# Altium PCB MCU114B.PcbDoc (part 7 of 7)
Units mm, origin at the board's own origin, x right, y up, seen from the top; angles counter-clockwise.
Board outline 105.51 x 58.76 mm, 8 copper layers (Top Layer, GND 2, Signal Layer 3, Power 4, Power 5, Signal Layer 6, GND 7, Bottom), stack 1.554 mm thick; 444 components, 418 nets, 1811 pads, 981 vias.
Unrouted connection lines stored in the file: 3.
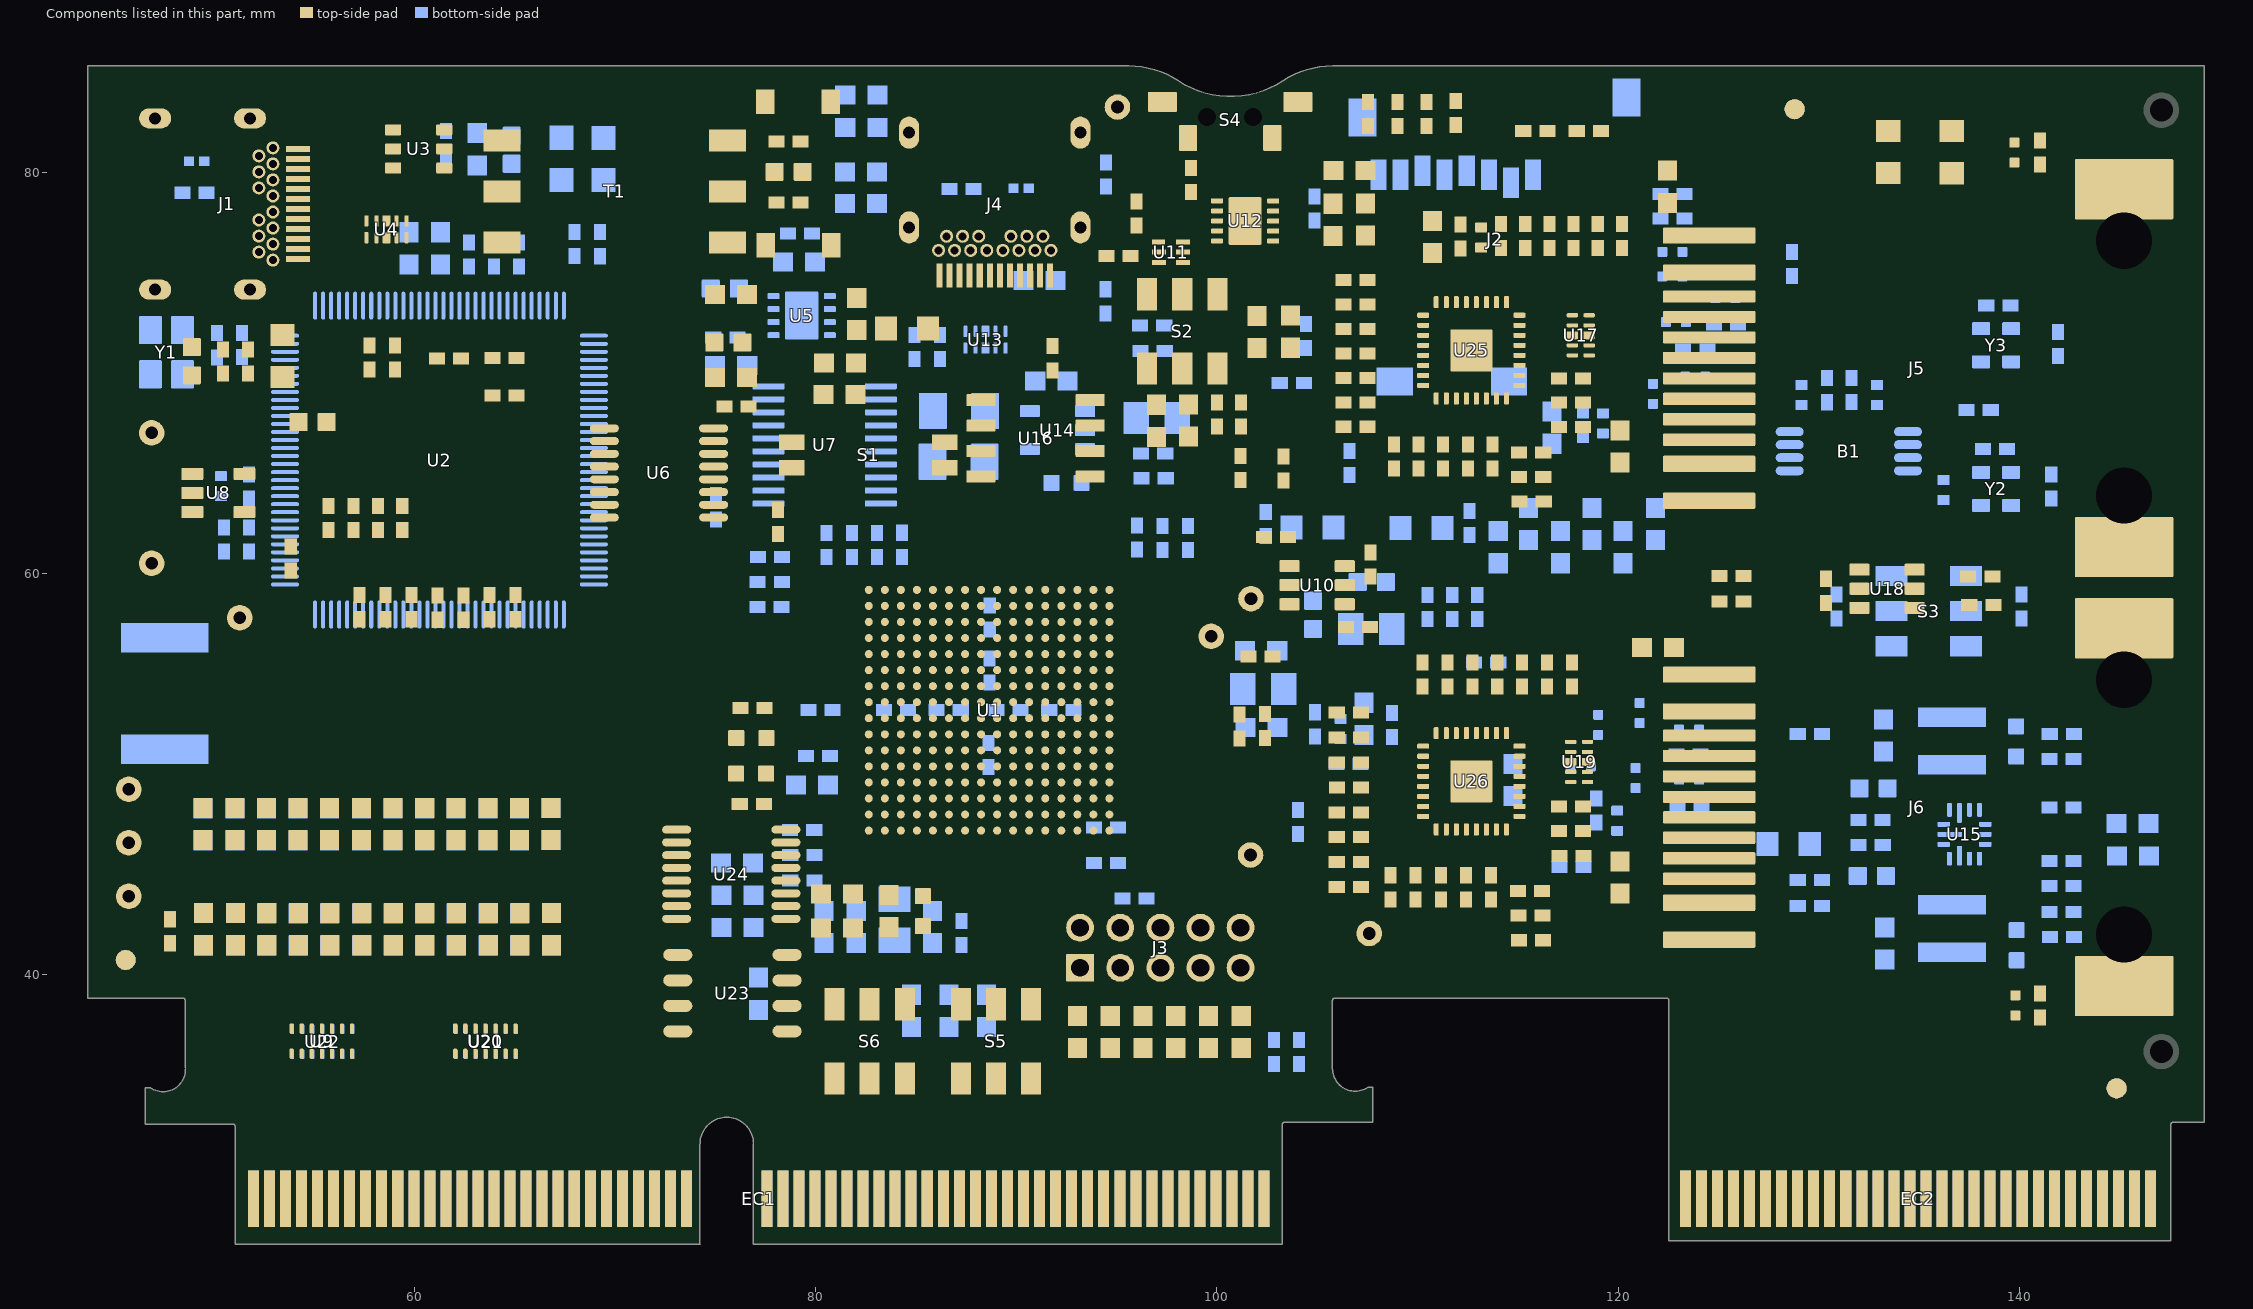
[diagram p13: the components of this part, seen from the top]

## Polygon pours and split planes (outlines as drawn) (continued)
EMU_GND on GND 7 "GND_7_EMU_GND_P189" (solid, remove dead copper, pour order 189): 43.783,85.148 70.452,85.148 70.452,59.973 66.442,55.963 43.657,55.963
GND on GND 7 "GND_7_GND_P223" (solid, remove dead copper, pour order 223): 43.481,52.064 67.785,52.064 73.961,58.241 73.961,84.83 148.917,84.83 148.917,35.541 148.917,32.595 147.811,32.595 147.331,32.115 147.331,26.271 122.576,26.271 122.051,26.797 122.051,38.31 105.609,38.31 105.711,38.207 105.711,34.627 106.346,34.119 107.336,34.119 107.336,32.367 107.336,32.115 107.334,32.112 102.842,32.112 102.842,26.169 102.818,26.194 76.654,26.194 76.654,31.575 75.8,32.429 74.685,32.429 73.961,31.706 73.961,26.474 51,26.474 50.873,26.347 50.873,32.239 46.504,32.239 46.173,32.571 46.173,34.094 47.749,34.094 48.616,34.961 48.616,39.008 43.481,39.008
VDDA_3V3 on Power 5 "POWER_5_VDDA_3V3_P176" (solid, remove dead copper, pour order 176): 48.146,39.484 47.803,39.827 47.803,49.513 48.484,50.194 66.968,50.194 68.129,49.032 75.097,49.032 75.097,52.534 77.367,54.804 82.273,54.804 84.984,52.093 86.443,52.093 86.648,51.889 86.648,50.477 87.626,49.499 87.626,48.556 89.404,46.778 89.404,42.463 88.116,41.175 77.476,41.175 76.412,40.111 76.412,32.825 74.684,32.825 74.054,32.194 74.054,27.013 51.121,27.013 50.86,27.274 50.888,27.302 50.888,32.513 46.839,32.513 46.528,32.825 46.722,33.02 46.722,34.305 48.599,34.305 48.616,34.323 48.599,39.37
VBUS_5V0 on Power 5 "POWER_5_VBUS_5V0_P207" (solid, remove dead copper, pour order 207): 85.351,80.411 95.068,80.411 95.068,70.492 95.066,70.494 91.334,70.494 91.334,68.476 91.307,68.449 91.311,68.444 93.56,68.444 93.56,63.922 93.543,63.939 85.5,63.939
ISO_Pout_5V0 on Power 5 "POWER_5_ISO_POUT_5V0_P218" (solid, remove dead copper, pour order 218): 74.304,74.642 75.946,74.642 75.946,71.543 80.714,71.543 80.714,78.912 81.962,80.16 81.962,84.64 74.297,84.64 74.279,84.658
EMU_3V3 on Power 5 "POWER_5_EMU_3V3_P228" (solid, remove dead copper, pour order 228): 44.126,84.97 70.663,84.97 70.663,60.184 66.391,55.912 44,55.912
3V3 on Power 5 "POWER_5_3V3_P246" (solid, remove dead copper, pour order 246): 43.799,52.128 68.049,52.128 74.073,58.432 74.192,85.427 149.234,85.427 149.234,36.139 149.234,33.192 148.128,33.192 147.648,32.712 147.648,26.868 122.894,26.868 122.368,27.394 122.368,38.907 105.926,38.907 106.029,38.805 106.029,35.224 106.664,34.716 107.653,34.716 107.653,32.964 107.653,32.712 107.651,32.71 103.159,32.71 103.159,26.767 103.135,26.792 76.971,26.792 76.971,32.173 76.117,33.027 75.002,33.027 74.279,32.303 74.279,26.944 51.19,26.944 50.86,27.274 50.86,32.837 46.821,32.837 46.49,33.168 46.49,34.691 48.066,34.691 48.625,35.25 48.625,39.161 43.799,39.161

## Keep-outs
Keep-Out Layer:
  text ".Layer_Name" at -19.432,-22.847 h1.52

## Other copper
Top Layer:
  pour cut-out: 127.135,34.648 128.291,34.648 128.291,34.083 127.223,34.083
  pour cut-out: 85.75,34.112 86.004,33.858 86.004,30.709 84.966,30.709 84.667,31.008
  pour cut-out: 84.734,35.916 85.743,35.916 85.75,35.923 85.75,34.112 84.887,34.112 84.811,34.188
  pour cut-out: 51.136,71.399 51.136,70.112 49.151,70.112 49.151,71.389
  pour cut-out: 101.552,34.068 102.235,33.386 102.235,32.639 104.343,34.747 103.226,35.865 103.226,35.742
  pour cut-out: 51.696,27.309 73.588,27.309 73.588,27.204 51.696,27.204
  pour cut-out: 77.526,27.309 102.518,27.309 102.428,27.219 102.428,27.204 77.526,27.204
  pour cut-out: 96.933,45.796 97.129,45.796 97.139,45.807 99.486,43.459 99.37,43.459 99.121,43.211 96.914,45.418 96.914,45.749
  pour cut-out: 82.92,49.011 82.92,48.889 83.486,48.324 83.124,47.963 82.282,47.963 82.091,48.153 82.919,48.98
  pour cut-out: 86.117,47.71 86.926,47.71 87.032,47.604 86.872,47.444 86.872,46.035 86.359,46.035 86.117,46.277
  pour cut-out: 85.368,49.47 85.536,49.47 86.648,49.47 86.648,47.593 86.648,47.71 86.388,47.71 85.371,47.71 85.371,47.937 85.368,49.327
  pour cut-out: 88.306,52.322 88.452,52.468 88.976,52.468 88.976,45.682 88.819,45.524 88.758,45.585 88.367,45.585 88.367,47.25 87.953,47.664 87.894,47.604 87.225,47.604 87.225,49.012 88.073,49.86 88.073,52.196 88.198,52.322
  pour cut-out: 89.43,53.521 94.965,53.521 94.965,53.001 94.977,52.989 94.96,52.972 89.25,52.972 89.25,53.341
  pour cut-out: 88.176,58.868 89.106,58.868 89.106,55.742 88.96,55.595 88.953,55.601 87.448,55.601 87.448,58.289 88.071,58.912
  pour cut-out: 73.673,67.424 73.762,67.335 74.218,67.335 74.218,62.584 74.198,62.564 74.062,62.699 73.622,62.699 73.622,67.373
  pour cut-out: 98.908,59.284 99.064,59.127 100.223,59.127 100.223,58.552 99.869,58.198 99.773,58.294 97.896,58.294 97.896,58.505 98.701,59.31
  text ".Layer_Name" at -18.618,-22.708 h1.52
Signal Layer 3:
  text ".Layer_Name" at -19.74,-23.183 h1.52
GND 2:
  text ".Layer_Name" at -18.851,-22.675 h1.52
GND 7:
  text ".Layer_Name" at -18.724,-22.599 h1.52
Signal Layer 6:
  text ".Layer_Name" at -18.419,-22.574 h1.52
Power 4:
  text ".Layer_Name" at -18.114,-22.955 h1.52
Power 5:
  text ".Layer_Name" at -18.724,-22.599 h1.52
Bottom:
  pour cut-out: 62.674,46.366 62.684,46.376 63.042,46.376 63.042,45.478 62.777,45.213
  pour cut-out: 81.022,42.565 82.723,42.565 82.728,42.57 82.728,43.002 81.051,43.002 81.026,42.977
  pour cut-out: 103.381,33.268 102.546,33.268 102.54,33.274 102.54,32.945 102.695,32.79
  pour cut-out: 98.783,59.57 98.783,59.136 98.806,59.113 98.744,59.051 98.404,59.051 98.323,59.131
  pour cut-out: 142.035,48.781 142.037,48.782 142.037,48.895 141.859,48.895 141.859,48.768
  pour cut-out: 80.254,72.973 80.433,73.152 81.763,73.152 81.763,72.626 80.82,71.683 80.248,71.683
  pour cut-out: 86.499,39.497 87.528,39.497 87.528,35.685 87.378,35.535 86.411,35.535
  pour cut-out: 76.891,68.416 76.908,68.432 78.552,68.432 79.07,67.913 79.07,67.513 79.375,67.208 79.375,64.17 78.845,63.64 78.733,63.752 76.891,63.752 76.891,67.676
  pour cut-out: 82.067,64.796 84.072,64.796 84.172,64.695 84.172,63.395 82.888,63.395 82.219,64.065 82.067,64.065
  pour cut-out: 80.045,67.209 82.079,69.242 84.093,69.242 84.172,69.163 84.172,67.295 81.606,67.295 81.037,66.726 80.092,66.726
  pour cut-out: 94.995,66.071 95.542,66.618 98.78,66.618 98.78,64.262 94.995,64.262
  pour cut-out: 136.372,33.954 136.451,34.033 136.867,34.033 136.867,32.787 136.917,32.737 136.697,32.517 136.443,32.517 136.443,33.883
  pour cut-out: 147.142,31.445 147.142,30.378 147.127,30.363 146.839,30.363 146.839,31.215 146.609,31.445
  text ".Layer_Name" at -18.597,-23.006 h1.52

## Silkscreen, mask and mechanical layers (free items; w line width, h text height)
Top Overlay:
  text "-----------------------------" at 70.344,85.778 h0.89 r269.64
  text "------------------------------" at 73.672,85.27 h0.89 r269.64
  text "ETH1_EARTH" at 140.208,83.696 h1.02
  text "5V0" at 94.132,81.423 h1.4
  text "P0" at 126.467,80.306 h1.4
  text "XRSn" at 99.924,79.924 h1.4
  text "0" at 95.072,74.536 h1.02
  text "1" at 101.183,74.53 h1.02
  text "POS 1" at 92.748,72.772 h1.02
  text "POS 2" at 92.748,70.844 h1.02
  text "0" at 95.072,69.434 h1.02
  text "1" at 101.183,69.429 h1.02
  text "ON" at 85.827,67.996 h1.02
  text "JTAG" at 76.046,66.278 h0.89
  text "UART" at 75.985,65.023 h0.89
  text "EMU_5V0" at 45.661,64.15 h1.4 r90
  text "ON" at 85.827,63.195 h1.02
  text "VDD_1V2" at 97.131,59.811 h1.4
  text "EMU_3V3" at 44.396,58.603 h1.4
  text "XRSn" at 95.656,56.429 h1.4
  text "Cold Side" at 66.565,56.249 h1.4 r47.05
  text "EMU_GND" at 48.163,56.209 h1.4
  text "-------" at 66.714,55.448 h0.89 r45.17
  text "-------------------------" at 44.069,55.283 h0.89
  text "Hot Side" at 70.43,53.076 h1.4 r45.91
  text "----------" at 68.289,51.936 h0.89 r46.53
  text "---------------------------" at 43.756,51.751 h0.89
  text "3V3" at 44.831,50.155 h1.4
  text "GND" at 44.372,47.392 h1.4
  text "VDDIO_3V3" at 95.685,47.075 h1.4
  text "HSEC_5V0" at 46.533,44.221 h1.4
  text "Int Vref_B" at 86.466,40.117 h1.4
  text "Ext Vref" at 80.418,40 h1.4
  text "ERRORSTS" at 104.064,39.335 h1.4
  text "1" at 79.877,39.037 h1.02
  text "0" at 85.487,39.042 h1.02
  text "1" at 86.132,39.037 h1.02
  text "0" at 91.574,38.985 h1.02
  text "P1" at 126.635,37.643 h1.4
  text "ETH1_EARTH" at 140.081,35.944 h1.02
  text "C2000 F28P65x controlCARD" at 124.115,34.258 h1.52
  text "1" at 79.773,33.878 h1.02
  text "0" at 85.377,33.884 h1.02
  text "1" at 86.022,33.878 h1.02
  text "0" at 91.464,33.827 h1.02
  text "57" at 76.953,32.555 h1.27
  text "55" at 72.974,32.539 h1.27
  text "179" at 145.771,32.532 h1.27
  text "1" at 51.764,32.524 h1.27
  text "119" at 101.401,32.517 h1.27
  text "121" at 122.707,32.524 h1.27
  text "Int Vref_A" at 79.891,32.46 h1.4
  text "Int Vref_C" at 86.762,32.46 h1.4
  text "REV B - 002" at 129.388,32.275 h1.52
  text ".Layer_Name" at -19.105,-22.523 h1.52
Bottom Overlay:
  text "-------------------------------" at 73.646,85.905 h0.89 r269.64
  text "-----------------------------" at 70.344,85.752 h0.89 r269.64
  text "1" at 132.497,60.685 h1.02
  text "1" at 138.71,60.685 h1.02
  text "GPIO 84" at 131.786,56.413 h1.02 r270
  text "GPIO 72" at 138.517,56.415 h1.02 r270
  text "-------" at 66.714,55.448 h0.89 r45.17
  text "-------------------------" at 44.12,55.283 h0.89
  text "0" at 132.165,55.293 h1.02
  text "0" at 138.378,55.293 h1.02
  text "BOOT" at 136.703,54.367 h1.02
  text "----------" at 68.289,51.936 h0.89 r46.5
  text "---------------------------" at 43.853,51.702 h0.89
  text "TMDSCNCD28P65X" at 125.374,42.443 h1.78
  text "'.PRJ_Number'.PCB_Rev" at 122.027,40.725 h1.78
  text "58" at 78.008,32.552 h1.27
  text "56" at 74.117,32.536 h1.27
  text "122" at 124.384,32.537 h1.27
  text "2" at 52.187,32.519 h1.27
  text "120" at 103.108,32.512 h1.27
  text "180" at 147.5,32.516 h1.27
  text ".Layer_Name" at -19.054,-22.777 h1.52
Top Paste:
  text ".Layer_Name" at -19.432,-22.847 h1.52
Bottom Paste:
  text ".Layer_Name" at -19.432,-22.847 h1.52
Top Solder:
  rectangle: 50.8,26.213 74.498,30.256
  rectangle: 122.276,26.213 147.803,30.256
  rectangle: 76.632,26.213 103.505,30.256
  text ".Layer_Name" at -19.432,-22.847 h1.52
  text ".Layer_Name" at -19.432,-22.847 h1.52
Bottom Solder:
  rectangle: 122.276,26.213 147.803,30.256
  rectangle: 50.8,26.213 74.473,30.256
  rectangle: 76.657,26.203 103.505,30.246
  text ".Layer_Name" at -19.432,-22.847 h1.52
Drill Guide:
  text ".Layer_Name" at -19.432,-22.847 h1.52
M1 Board Outline:
  lines w0.254: 48.433,35.338 48.433,38.716 43.582,38.716 43.582,85.446 95.682,85.446 ; 48.445,35.339 cw(c47.456,35.29) 46.858,34.5 46.452,34.5 46.452,32.436 50.927,32.436 50.927,26.568 ; 51.075,26.442 74.23,26.442 ; 74.353,26.606 74.353,31.546 ; 74.355,31.571 cw(c75.561,31.561) 76.767,31.571 76.767,26.563 ; 76.896,26.434 103.381,26.435 ; 95.606,85.446 cw(c95.606,80.831) 98.146,84.684 ccw(c100.686,88.536) 103.226,84.684 cw(c105.766,80.831) 105.766,85.446 ; 103.381,26.584 103.381,32.434 ; 103.381,32.519 107.894,32.519 107.894,34.525 107.488,34.525 cw(c106.891,35.316) 105.9,35.313 ; 105.842,85.446 149.347,85.446 149.347,32.521 147.686,32.521 147.686,26.626 122.405,26.626 122.405,38.716 105.888,38.716 105.888,37.792 105.888,35.313
  text ".Layer_Name" at -19.432,-22.847 h1.52
M2 Board Dimensions:
  rectangle: -34.088,-8.026 -30.913,-4.851
  rectangle: -30.913,-11.201 -21.388,-8.026
  lines w0.127: 50.77,33.307 51.024,33.053 ; 51.278,33.307 51.024,33.053 ; 55.342,34.196 51.659,34.196 51.024,33.561 51.024,33.053 ; 103.856,31.783 103.856,32.164 ; 104.237,32.164 103.856,32.164 ; 104.237,39.657 104.237,38.768 104.745,38.768 105.507,38.768 ; 105.253,38.514 105.507,38.768 ; 105.253,39.022 105.507,38.768 ; 110.206,40.038 110.46,39.784 122.525,39.784 122.525,39.276 122.525,38.895 ; 113.635,17.559 113.635,21.877 104.618,30.894 104.618,31.402 103.856,32.164 ; 122.271,39.149 122.525,38.895 ; 122.779,39.149 122.525,38.895 ; 146.782,35.466 146.782,34.831 147.29,34.323 147.798,33.815 147.798,33.434 147.798,32.799 ; 147.544,33.053 147.798,32.799 ; 148.052,33.053 147.798,32.799
  lines w0.178: -34.088,-8.026 -8.688,-8.026 ; -30.913,-11.201 -30.913,-4.851 ; -27.738,-11.201 -27.738,-4.851 ; -21.388,-11.201 -21.388,-4.851 ; -15.038,-11.201 -15.038,-4.851 ; -34.088,-11.201 -8.688,-11.201 -8.688,-4.851 -34.088,-4.851 -34.088,-11.201
  lines w0.254: 48.865,39.784 48.865,39.276 ; 49.373,39.276 48.865,39.276 ; 51.278,39.657 49.246,39.657 48.865,39.276 ; 215.797,4.725 217.524,4.725 ; 216.864,3.988 217.55,4.699 ; 216.864,5.487 217.55,4.725 ; 217.728,38.888 219.455,40.97 ; 217.778,3.531 217.778,11.71 ; 217.778,12.751 219.048,11.379 221.842,11.379 223.036,12.827 ; 217.778,12.802 217.778,38.964 ; 219.429,40.996 221.055,38.786 ; 219.887,8.992 221.614,8.992 ; 220.953,8.255 221.639,8.966 ; 220.953,9.754 221.639,8.992 ; 221.08,38.761 222.909,41.047 ; 221.868,3.531 221.868,10.694 ; 223.036,12.802 223.036,38.964 223.036,41.123 ; 223.062,3.531 223.062,11.71 ; 223.213,29.328 cw(c221.792,11.354) 232.951,25.515 ; 223.261,29.293 ccw(c226.81,35.253) 224.553,28.694 ; 223.265,4.801 223.951,4.039 ; 223.265,4.826 223.951,5.537 ; 223.265,29.464 cw(c224.089,25.045) 224.858,29.474 ; 223.316,4.826 225.043,4.826 ; 223.316,8.966 224.001,8.204 ; 223.316,8.992 224.001,9.703 ; 223.366,8.992 225.094,8.992 ; 223.722,13.792 235.482,28.321 ; 231.596,25.883 ccw(c235.089,34.53) 232.984,25.444 ; 232.034,26.729 cw(c229.066,23.339) 233.018,25.502
  text "X2" at 107.412,42.705 h1.52
  text "R 39.00" at 101.723,40.469 h1.52
  text "R 39.00" at 52.04,39.149 h1.52
  text "R 39.00" at 138.654,35.974 h1.52
  text "R 39.00" at 56.104,33.307 h1.52
  text "30" at 228.015,29.845 h1.52
  text "R 39.00" at 110.333,15.4 h1.52
  text "18MIL" at 226.135,8.281 h1.52
  text "62MIL" at 225.957,4.115 h1.52
  text "GOLD FINGER" at 213.74,-1.905 h1.52
  text "SIDE VIEW" at 215.111,-4.775 h1.52
  text ".Layer_Name" at -19.432,-22.847 h1.52
M3 3D STEP Top:
  text ".Layer_Name" at -19.432,-22.847 h1.52
M4 3D STEP Bottom:
  text ".Layer_Name" at -19.432,-22.847 h1.52
M5 Assembly Top:
  lines w0.254: -41.505,-24.668 126.135,-24.668 ; -41.505,-19.503 126.186,-19.503 ; -41.505,-14.338 -41.505,-29.832 60.222,-29.832 126.186,-29.832 126.186,-14.338 -41.492,-14.338 -41.492,-29.832 -1.474,-29.832 ; 21.106,-29.832 21.106,-14.338 ; 53.288,-19.503 53.288,-14.338 ; 74.624,-19.503 74.624,-14.338 ; 90.423,-29.997 90.423,-24.845
  text "COMPONENTS MARKED 'DNP' SHOULD NOT BE POPULATED." at -4.789,-9.131 h1.52
  text "ASSEMBLY VARIANT:" at -4.802,-12.065 h1.52
  text ".VariantName" at 21.513,-12.065 h1.52
  text "PCB VIEWED FROM TOP SIDE" at -39.892,-17.695 h1.52
  text "BOARD #:" at 23.011,-17.695 h1.52
  text ".PRJ_Number" at 36.867,-17.695 h1.52
  text "REV:" at 58.317,-17.695 h1.52
  text ".PCB_Rev" at 65.721,-17.695 h1.52
  text "SVN REV:" at 79.602,-17.695 h1.52
  text "TID #:" at 23.011,-22.86 h1.52
  text ".TID" at 36.867,-22.86 h1.52
  text "PLOT NAME =" at -39.892,-28.075 h1.52
  text ".plot_File_Name" at -19.432,-28.075 h1.52
  text "GENERATED    :" at 23.062,-28.075 h1.52
  text ".Print_Date" at 45.147,-28.075 h1.52
  text ".Print_Time" at 63.664,-28.075 h1.52
  text "TEXAS INSTRUMENTS" at 95.782,-28.075 h1.52
M6 Assembly Bottom:
  lines w0.254: -41.518,-19.516 126.173,-19.516 ; -41.467,-24.68 126.173,-24.68 ; -5.754,-30.01 -5.754,-24.858 ; 10.044,-19.516 10.044,-14.351 ; 31.38,-19.516 31.38,-14.351 ; 63.562,-29.845 63.562,-14.351 ; 86.143,-29.845 126.161,-29.845 126.161,-14.351 -41.518,-14.351 -41.518,-29.845 24.446,-29.845 126.173,-29.845 126.173,-14.351
  text "COMPONENTS MARKED 'DNP' SHOULD NOT BE POPULATED." at 120.903,-9.118 h1.52
  text ".VariantName" at 94.385,-12.065 h1.52
  text "ASSEMBLY VARIANT:" at 120.776,-12.065 h1.52
  text "SVN REV:" at 5.066,-17.708 h1.52
  text ".PCB_Rev" at 18.947,-17.708 h1.52
  text "REV:" at 26.351,-17.708 h1.52
  text ".PRJ_Number" at 47.802,-17.708 h1.52
  text "BOARD #:" at 61.657,-17.708 h1.52
  text ".TID" at 47.802,-22.873 h1.52
  text "TID #:" at 61.657,-22.873 h1.52
  text "TEXAS INSTRUMENTS" at -11.114,-28.088 h1.52
  text ".Print_Time" at 21.005,-28.088 h1.52
  text ".Print_Date" at 39.521,-28.088 h1.52
  text "GENERATED    :" at 61.606,-28.088 h1.52
  text ".plot_File_Name" at 104.101,-28.088 h1.52
  text "PLOT NAME =" at 124.56,-28.088 h1.52
M9 Title Sheet:
  drawing of 57 lines, arcs and shapes, not listed
  text "1" at -15.296,203.086 h1.78
  text "2" at 48.094,203.086 h1.78
  text "3" at 111.323,203.086 h1.78
  text "4" at 174.992,203.086 h1.78
  text "5" at 238.467,203.086 h1.78
  text "6" at 302.094,203.086 h1.78
  text "A" at -44.667,174.054 h1.78
  text "A" at 331.253,174.054 h1.78
  text "B" at -44.667,113.602 h1.78
  text "B" at 331.253,113.602 h1.78
  text "C" at -44.667,53.277 h1.78
  text "C" at 331.253,53.277 h1.78
  text "PROJECT TITLE:" at 254.037,6.007 h1.14
  text ".PRJ_Title" at 255.307,2.621 h1.78
  text "DESIGNED FOR:" at 254.037,-1.638 h1.14
  text ".PRJ_Customer" at 255.307,-5.194 h1.78
  text "D" at -44.667,-6.921 h1.78
  text "D" at 331.253,-6.921 h1.78
  text "FILE NAME:" at 254.037,-9.258 h1.14
  text ".PCB_File_Name_No_Path" at 255.307,-12.306 h1.78
  text "Texas Instruments (TI) and/or its licensors do not warrant the accuracy or completeness of this specification" at 127.812,-16.417 h1.14
  text "ENGINEER:" at 254.037,-16.624 h1.14
  text "LAYOUT BY:" at 292.264,-16.624 h1.14
  text "or any information contained therein. TI and/or its licensors do not warrant that this design will meet" at 126.669,-19.279 h1.14
  text ".PRJ_Engineer" at 255.307,-20.561 h1.78
  text ".PCB_Layout" at 293.547,-20.561 h1.78
  text "the specifications, will be suitable for your application or fit for any particular purpose, or will operate in" at 126.669,-22.14 h1.14
  text ".Layer_Name" at -19.432,-22.847 h1.52
  text "ALTIUM DESIGNER VERSION:" at 292.264,-24.498 h1.14
  text "an implementation. TI and/or its licensors do not warrant that the design is production worthy. You should" at 126.669,-25.002 h1.14
  text "completely validate and test your design implementation to confirm the system functionality for your application." at 127.812,-27.864 h1.14
  text ".print_Scale" at 255.307,-27.885 h1.78
  text ".Application_BuildNumber" at 293.547,-27.885 h1.78
  text "1" at -15.296,-33.134 h1.78
  text "2" at 48.094,-33.134 h1.78
  text "3" at 111.323,-33.134 h1.78
  text "4" at 174.992,-33.134 h1.78
  text "5" at 238.467,-33.134 h1.78
  text "6" at 302.094,-33.134 h1.78
M10 Fab Notes:
  drawing of 185 lines, arcs and shapes, not listed
  text "DESIGN INFORMATION" at 280.415,163.962 h1.52
  text "5" at 291.943,160.688 h1.52
  text "MIN. TRACK WIDTH:" at 264.043,160.606 h1.52
  text "MIL" at 295.819,160.606 h1.52
  text "4" at 292.197,157.64 h1.52
  text "MIN. CLEARANCE:" at 264.043,157.453 h1.52
  text "MIL" at 295.819,157.453 h1.52
  text "MIN. VIA PAD SIZE:" at 264.043,154.3 h1.52
  text "18" at 291.126,154.3 h1.52
  text "MIL" at 295.819,154.3 h1.52
  text "0.05mm (2MIL)" at 281.696,151 h1.52
  text "MINIMUM ANNULAR RING" at 255.681,150.792 h1.52
  text "EXTERNAL" at 299.68,150.792 h1.52
  text "PER" at 260.761,147.994 h1.52
  text "IPC-D-275 CLASS 2 LEVEL C" at 266.349,147.994 h1.52
  text "MIL, HOLES" at 304.15,145.442 h1.52
  text "+/-" at 294.182,145.224 h1.52
  text "+/-" at 315.873,145.224 h1.52
  text "REGISTRATION TOLERANCES:" at 255.681,145.197 h1.52
  text "METAL" at 286.155,145.197 h1.52
  text "5" at 300.791,145.197 h1.52
  text "3" at 321.949,145.197 h1.52
  text "MIL" at 324.902,145.197 h1.52
  text "HOLE SIZE TOLERANCE (UNLESS OTHERWISE SPECIFIED):" at 255.681,142.7 h1.52
  text "+/-" at 315.873,142.627 h1.52
  text "3" at 321.949,142.6 h1.52
  text "MIL" at 324.902,142.6 h1.52
  text "MATERIAL:" at 253.782,139.104 h1.52
  text "FR-4 High Tg" at 278.837,135.839 h1.52
  text "X" at 275.169,135.636 h1.52
  text "FR-408" at 264.475,135.522 h1.52
  text "OTHER" at 302.27,135.522 h1.52
  text "62 MIL (1.57mm) +/-10%" at 272.606,131.889 h1.52
  text "X" at 269.555,131.826 h1.52
  text "THICKNESS:" at 255.681,131.68 h1.52
  text "OTHER" at 305.242,131.68 h1.52
  text "TOLERANCE:" at 255.681,128.167 h1.52
  text "X" at 277.226,128.167 h1.52
  text "ANSI IPC-6012 TYPE 3 CLASS 2" at 281.748,128.167 h1.52
  text "OTHER +/-" at 281.747,124.504 h1.52
  text "BOW & TWIST:" at 255.681,120.816 h1.52
  text "X" at 277.226,120.816 h1.52
  text "ANSI IPC-6012 TYPE 3 CLASS 2" at 281.748,120.816 h1.52
  text "OTHER +/-" at 281.747,117.09 h1.52
  text "DRILLING:" at 253.782,113.773 h1.52
  text "NC_DRILL FILES" at 298.511,111.101 h1.52
  text "REFERENCE:" at 255.681,111.001 h1.52
  text "X" at 272.375,110.998 h1.52
  text "AS SHOWN" at 276.896,111.001 h1.52
  text "X" at 295.26,111.001 h1.52
  text "OTHER" at 306.08,107.388 h1.52
  text "PTH COPPER THICKNESS:" at 255.673,107.298 h1.52
  text "X" at 284.609,107.298 h1.52
  text "20-30 um" at 287.86,107.298 h1.52
  text "BOARD FINISH:" at 253.782,103.549 h1.52
  text "SILKSCREEN:" at 257.724,100.752 h1.52
  text "X" at 282.052,100.752 h1.52
  text "TOP" at 285.024,100.752 h1.52
  text "X" at 295.006,100.752 h1.52
  text "BOTTOM" at 298.003,100.752 h1.52
  text "SILKSCREEN COLOR:" at 257.724,96.81 h1.52
  text "X" at 282.027,96.81 h1.52
  text "WHITE" at 285.024,96.81 h1.52
  text "OTHER" at 298.003,96.81 h1.52
  text "BLUE" at 314.64,93.42 h1.52
  text "GREEN" at 288.351,93.166 h1.52
  text "X" at 300.34,93.166 h1.52
  text "OTHER" at 304.048,93.166 h1.52
  text "SOLDER RESIST COLOR:" at 257.724,92.992 h1.52
  text "X" at 300.35,89.306 h1.52
  text "MATTE" at 288.351,89.248 h1.52
  text "SEMI-GLOSS" at 304.037,89.232 h1.52
  text "IMMERSION GOLD (ENIG)" at 280.731,84.86 h1.52
  text "ENEPIG" at 314.705,84.677 h1.52
  text "SURFACE FINISH:" at 253.782,84.651 h1.52
  text "X" at 276.21,84.651 h1.52
  text "IMM. TIN/SILVER OR EQUIV" at 262.152,81.163 h1.52
  text "HARD GOLD OVER NICKEL 30u/80u, ON EDGEFINGERS" at 271.662,77.277 h1.52
  text "X" at 258.176,77.031 h1.52
  text "OTHER" at 262.697,76.999 h1.52
  text "ARRAY/PANEL:" at 253.782,73.561 h1.52
  text "CUT AND TRIM PER M1 BOARD OUTLINE" at 280.731,73.352 h1.52
  text "N.C. ROUTE" at 280.731,69.898 h1.52
  text "X" at 298.207,69.898 h1.52
  text "V. SCORE" at 302.728,69.898 h1.52
  text "CERTIFICATION:" at 253.782,66.619 h1.52
  text "MATERIALS AND WORKMANSHIP FOR ALL PCBS" at 272.197,66.619 h1.52
  text "TO MEET OR EXCEED THE REQUIREMENTS OF:" at 272.197,64.229 h1.52
  text "X" at 262.99,60.962 h1.52
  text "ANSI IPC-A-600F CLASS ->" at 266.241,60.962 h1.52
  text "X" at 308.1,60.962 h1.52
  text "2" at 310.894,60.962 h1.52
  text "1" at 302.893,60.924 h1.52
  text "3" at 319.885,60.924 h1.52
  text "RJ1 and RJ2 : NPTH on SMT pads are intentional per manufacturers footprint.  SMT pad copper may be pulled back 5-8Mil from holes as needed for processing." at 174.727,58.344 h1.5
  text "X" at 283.614,57.211 h1.52
  text "RoHS" at 286.865,57.211 h1.52
  text "OTHER" at 303.233,57.211 h1.52
  text "PER ORDER" at 313.318,57.211 h1.52
  text "ALL BOARDS MUST MEET OR EXCEED UL94-V0 REQUIREMENTS." at 254.481,53.304 h1.52
  text "PCB MUST BEAR THE UL94V-0 UL REGISTERED MATERIAL ID NUMBER" at 254.481,50.356 h1.52
  text "ADDITIONAL REQUIREMENTS:" at 253.782,46.052 h1.52
  text "REQUIRED" at 299.045,42.967 h1.52
  text "BARE BOARD ELEC. TEST:" at 254.157,42.895 h1.52
  text "NONE" at 287.323,42.895 h1.52
  text "X" at 311.098,42.901 h1.52
  text "PER ORDER" at 314.081,42.895 h1.52
  text "X" at 255.575,36.601 h1.52
  text "ALL LAYERS 6.1 MIL WIDE, 6 MIL SPACE / TRACES REQUIRE 90 OHM DIFFERENTIAL IMPEDANCE" at 260.782,35.001 h1.52
  text "X" at 255.649,31.524 h1.52
  text "ALL LAYERS 4.9 MIL WIDE, 6 MIL SPACE / TRACES REQUIRE 50 OHM DIFFERENTIAL IMPEDANCE" at 258.623,30.251 h1.52
  text "X" at 255.751,26.545 h1.52
  text "OUTER LAYERS 6.2 MIL WIDE, 6 MIL SPACE / TRACES REQUIRE 100 OHM DIFFERENTIAL IMPEDANCE" at 258.826,25.324 h1.52
  text "X" at 255.801,22.354 h1.52
  text "ALL LAYERS 5.2 MIL WIDE, 6 MIL SPACE / TRACES REQUIRE 50 OHM SE  IMPEDANCE MATCHING" at 260.629,20.955 h1.52
  text ".Layer_Name" at -19.432,-22.847 h1.52
M11 Gerber Information:
  lines w0.254: -41.505,-24.668 126.135,-24.668 ; -41.505,-19.503 126.186,-19.503 ; -41.505,-14.338 -41.505,-29.832 60.222,-29.832 126.186,-29.832 126.186,-14.338 -41.492,-14.338 -41.492,-29.832 -1.474,-29.832 ; 21.106,-29.832 21.106,-14.338 ; 53.288,-19.503 53.288,-14.338 ; 74.624,-19.503 74.624,-14.338 ; 90.423,-29.997 90.423,-24.845
  text "ALL ARTWORK VIEWED FROM TOP SIDE" at -39.892,-17.695 h1.52
  text "BOARD #:" at 23.011,-17.695 h1.52
  text ".PRJ_Number" at 36.867,-17.695 h1.52
  text "REV:" at 58.317,-17.695 h1.52
  text ".PCB_Rev" at 65.721,-17.695 h1.52
  text "SVN REV:" at 79.602,-17.695 h1.52
  text "LAYER NAME =" at -39.892,-22.847 h1.52
  text "TID #:" at 23.011,-22.86 h1.52
  text ".TID" at 36.867,-22.86 h1.52
  text "PLOT NAME =" at -39.892,-28.075 h1.52
  text ".plot_File_Name" at -19.432,-28.075 h1.52
  text "GENERATED    :" at 23.062,-28.075 h1.52
  text ".Print_Date" at 45.147,-28.075 h1.52
  text ".Print_Time" at 63.664,-28.075 h1.52
  text "TEXAS INSTRUMENTS" at 95.782,-28.075 h1.52
M12 Stackup:
  drawing of 503 lines, arcs and shapes, not listed
  text "Layer" at 135.162,173.253 h1.52
  text "Name" at 145.574,173.253 h1.52
  text "Material" at 169.443,173.253 h1.52
  text "Thickness" at 191.281,173.253 h1.52
  text "Constant" at 207.787,173.253 h1.52
  text "Board Layer Stack" at 222.262,173.253 h1.52
  text "Top Overlay" at 145.574,170.205 h1.52
  text "Top Solder" at 145.574,167.157 h1.52
  text "Solder Resist" at 169.443,167.157 h1.52
  text "0.50mil" at 191.281,167.157 h1.52
  text "3.6" at 207.787,167.157 h1.52
  text "1" at 135.162,164.109 h1.52
  text "Top Layer" at 145.574,164.109 h1.52
  text "CF-004" at 169.443,164.109 h1.52
  text "1.40mil" at 191.281,164.109 h1.52
  text "Dielectric 1" at 145.574,161.061 h1.52
  text "FR-4" at 169.443,161.061 h1.52
  text "5.00mil" at 191.281,161.061 h1.52
  text "3.7" at 207.787,161.061 h1.52
  text "2" at 135.162,158.013 h1.52
  text "GND 2" at 145.574,158.013 h1.52
  text "CF-004" at 169.443,158.013 h1.52
  text "1.40mil" at 191.281,158.013 h1.52
  text "Dielectric 2" at 145.574,154.965 h1.52
  text "FR-4" at 169.443,154.965 h1.52
  text "10.00mil" at 191.281,154.965 h1.52
  text "3.7" at 207.787,154.965 h1.52
  text "3" at 135.162,151.917 h1.52
  text "Signal Layer 3" at 145.574,151.917 h1.52
  text "CF-004" at 169.443,151.917 h1.52
  text "1.40mil" at 191.281,151.917 h1.52
  text "Dielectric 3" at 145.574,148.869 h1.52
  text "FR-4" at 169.443,148.869 h1.52
  text "5.00mil" at 191.281,148.869 h1.52
  text "3.7" at 207.787,148.869 h1.52
  text "4" at 135.162,145.821 h1.52
  text "Power 4" at 145.574,145.821 h1.52
  text "CF-004" at 169.443,145.821 h1.52
  text "1.40mil" at 191.281,145.821 h1.52
  text "Dielectric 4" at 145.574,142.773 h1.52
  text "FR-4" at 169.443,142.773 h1.52
  text "10.00mil" at 191.281,142.773 h1.52
  text "3.7" at 207.787,142.773 h1.52
  text "5" at 135.162,139.725 h1.52
  text "Power 5" at 145.574,139.725 h1.52
  text "CF-004" at 169.443,139.725 h1.52
  text "1.40mil" at 191.281,139.725 h1.52
  text "Dielectric 5" at 145.574,136.677 h1.52
  text "FR-4" at 169.443,136.677 h1.52
  text "5.00mil" at 191.281,136.677 h1.52
  text "3.7" at 207.787,136.677 h1.52
  text "6" at 135.162,133.629 h1.52
  text "Signal Layer 6" at 145.574,133.629 h1.52
  text "CF-004" at 169.443,133.629 h1.52
  text "1.40mil" at 191.281,133.629 h1.52
  text "Dielectric 6" at 145.574,130.581 h1.52
  text "FR-4" at 169.443,130.581 h1.52
  text "10.00mil" at 191.281,130.581 h1.52
  text "3.7" at 207.787,130.581 h1.52
  text "7" at 135.162,127.533 h1.52
  text "GND 7" at 145.574,127.533 h1.52
  text "CF-004" at 169.443,127.533 h1.52
  text "1.40mil" at 191.281,127.533 h1.52
  text "Dielectric 7" at 145.574,124.485 h1.52
  text "FR-4" at 169.443,124.485 h1.52
  text "5.00mil" at 191.281,124.485 h1.52
  text "3.7" at 207.787,124.485 h1.52
  text "8" at 135.162,121.437 h1.52
  text "Bottom" at 145.574,121.437 h1.52
  text "CF-004" at 169.443,121.437 h1.52
  text "1.40mil" at 191.281,121.437 h1.52
  text "Bottom Solder" at 145.574,118.389 h1.52
  text "Solder Resist" at 169.443,118.389 h1.52
  text "0.50mil" at 191.281,118.389 h1.52
  text "3.6" at 207.787,118.389 h1.52
  text "Bottom Overlay" at 145.574,115.341 h1.52
  text ".Layer_Name" at -19.432,-22.847 h1.52
M13 Component Bodies Top:
  text ".Layer_Name" at -19.432,-22.847 h1.52
M14 Component Bodies Bottom:
  text ".Layer_Name" at -19.432,-22.847 h1.52
M15 Courtyards Top:
  text ".Layer_Name" at -19.432,-22.847 h1.52
M16 Courtyards Bottom:
  text ".Layer_Name" at -19.432,-22.847 h1.52
Drill Drawing:
  circle w0.254: c-30.915,151.418 r0.847
  circle w0.254: c-30.915,136.178 r0.508
  circle w0.254: c-30.915,136.178 r0.847
  lines w0.254: -31.761,131.945 -31.338,131.945 -31.338,131.521 -30.491,131.521 -30.491,131.945 -30.068,131.945 -30.068,132.791 -30.491,132.791 -30.491,133.215 -31.338,133.215 -31.338,132.791 -31.761,132.791 -31.761,131.945 ; -31.761,139.565 -31.338,139.565 -30.915,139.141 -30.491,139.565 -30.068,139.565 -30.491,139.988 -30.068,140.411 -30.491,140.411 -30.915,140.835 -31.338,140.411 -31.761,140.411 -31.338,139.988 -31.761,139.565 ; -31.761,142.951 -30.915,143.375 -30.068,142.951 -30.491,143.798 -30.068,144.645 -30.915,144.221 -31.761,144.645 -31.338,143.798 -31.761,142.951 ; -31.761,146.761 -30.068,146.761 -30.068,148.455 -31.761,148.455 -31.761,146.761 ; -31.761,156.075 -30.068,156.075 -30.915,154.381 -31.761,156.075 ; -31.761,159.038 -30.915,158.191 -30.068,159.038 -30.915,159.885 -31.761,159.038 ; -31.761,162.001 -31.761,162.425 -31.338,162.848 -31.761,163.271 -31.761,163.695 -31.338,163.695 -30.915,163.271 -30.491,163.695 -30.068,163.695 -30.068,163.271 -30.491,162.848 -30.068,162.425 -30.068,162.001 -30.491,162.001 -30.915,162.425 -31.338,162.001 -31.761,162.001
  lines w0.305: -33.28,130.378 116.488,130.378 ; -33.28,164.668 116.488,164.668 ; -19.288,126.568 -19.288,168.478 ; -2.782,126.568 -2.782,168.478 ; 26.165,126.568 26.165,168.478 ; 39.014,126.568 39.014,168.478 ; 57.653,126.568 57.653,168.478 ; 87.87,126.568 87.87,168.478 ; -33.28,126.568 116.488,126.568 116.488,168.478 -33.28,168.478 -33.28,126.568
  text "Symbol" at -30.994,165.811 h1.83
  text "Count" at -18.145,165.811 h1.83
  text "Hole Size" at -1.639,165.811 h1.83
  text "Plated" at 27.308,165.811 h1.83
  text "Hole Type" at 40.157,165.811 h1.83
  text "Drill Layer Pair" at 58.796,165.811 h1.83
  text "Hole Tolerance" at 89.013,165.811 h1.83
  text "18" at -18.145,162.001 h1.52
  text "7.87mil (0.200mm)" at -1.639,162.001 h1.52
  text "PTH" at 27.308,162.001 h1.52
  text "Round" at 40.157,162.001 h1.52
  text "Top Layer - Bottom" at 58.796,162.001 h1.52
  text "963" at -18.145,158.191 h1.52
  text "8.00mil (0.203mm)" at -1.639,158.191 h1.52
  text "PTH" at 27.308,158.191 h1.52
  text "Round" at 40.157,158.191 h1.52
  text "Top Layer - Bottom" at 58.796,158.191 h1.52
  text "28" at -18.145,154.381 h1.52
  text "15.75mil (0.400mm)" at -1.639,154.381 h1.52
  text "PTH" at 27.308,154.381 h1.52
  text "Round" at 40.157,154.381 h1.52
  text "Top Layer - Bottom" at 58.796,154.381 h1.52
  text "8" at -18.145,150.571 h1.52
  text "23.62mil (0.600mm)" at -1.639,150.571 h1.52
  text "PTH" at 27.308,150.571 h1.52
  text "Slot" at 40.157,150.571 h1.52
  text "Top Layer - Bottom" at 58.796,150.571 h1.52
  text "11" at -18.145,146.761 h1.52
  text "25.00mil (0.635mm)" at -1.639,146.761 h1.52
  text "PTH" at 27.308,146.761 h1.52
  text "Round" at 40.157,146.761 h1.52
  text "Top Layer - Bottom" at 58.796,146.761 h1.52
  text "10" at -18.145,142.951 h1.52
  text "35.04mil (0.890mm)" at -1.639,142.951 h1.52
  text "PTH" at 27.308,142.951 h1.52
  text "Round" at 40.157,142.951 h1.52
  text "Top Layer - Bottom" at 58.796,142.951 h1.52
  text "2" at -18.145,139.141 h1.52
  text "35.43mil (0.900mm)" at -1.639,139.141 h1.52
  text "NPTH" at 27.308,139.141 h1.52
  text "Round" at 40.157,139.141 h1.52
  text "Top Layer - Bottom" at 58.796,139.141 h1.52
  text "2" at -18.145,135.331 h1.52
  text "45.00mil (1.143mm)" at -1.639,135.331 h1.52
  text "PTH" at 27.308,135.331 h1.52
  text "Round" at 40.157,135.331 h1.52
  text "Top Layer - Bottom" at 58.796,135.331 h1.52
  text "4" at -18.145,131.521 h1.52
  text "110.24mil (2.800mm)" at -1.639,131.521 h1.52
  text "NPTH" at 27.308,131.521 h1.52
  text "Round" at 40.157,131.521 h1.52
  text "Top Layer - Bottom" at 58.796,131.521 h1.52
  text "+1.97mil/-1.18mil" at 89.013,131.521 h1.52
  text "1046 Total" at -18.145,127.711 h1.52
  text "Slot definitions :" at -30.994,124.029 h1.52
  text "Routed Path Length" at -4.764,124.029 h1.52
  text "= Calculated from tool start centre position to tool end centre position." at 23.244,124.029 h1.52
  text "Hole Length" at -4.764,121.49 h1.52
  text "= Routed Path Length + Tool Size = Slot length as defined in the PCB layout" at 12.833,121.49 h1.52
  text ".Layer_Name" at -19.432,-22.847 h1.52
M17 Embedded Cavity:
  text ".Layer_Name" at -19.432,-22.847 h1.52
M18 Embedded Assembly:
  text ".Layer_Name" at -19.432,-22.847 h1.52
M19 Embedded Keepout:
  text ".Layer_Name" at -19.432,-22.847 h1.52

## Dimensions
-34.088,-11.201 to -8.688,-11.201 on M2 Board Dimensions
105.775,35.254 to 43.582,85.446 on M2 Board Dimensions
43.557,86.366 to 149.322,86.366 on M2 Board Dimensions
107.767,34.398 to 147.762,26.677 on M2 Board Dimensions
